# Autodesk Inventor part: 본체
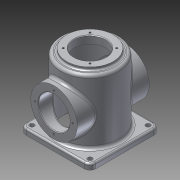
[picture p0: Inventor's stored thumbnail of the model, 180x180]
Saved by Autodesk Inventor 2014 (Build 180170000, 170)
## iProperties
Created: 2015-10
Part Number: 본체
Material: 알루미늄 6061
Document SubType Name: Modeling
Designer: USER
Density: 2.71 g/cm^3
Appearance: 알루미늄 - 평지
Mass: 982.687 g
Surface Area: 1041.97 cm^2
Volume: 362.615 cm^3
Author: USER
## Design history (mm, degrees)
sketch "스케치1"
  geometry: C1 r 50 at (0, 0); 1 further point
  constraints: 1 centre point, 1 coincident
  dimensions: "d0" = 100 diameter of C1
extrude "돌출1" new body sketch "스케치1" distance "d1" = 120; taper "d2" = 0 deg
sketch "스케치2"
  geometry: C1 r 50 at (0, 0) reference; C2 r 40 at (0, 0)
  constraints: 1 centre point, 1 coincident
  dimensions: "d3" = 80 diameter of C2
extrude "돌출2" join sketch "스케치2" distance "d4" = 5; taper "d5" = 0 deg
sketch "스케치3"
  geometry: C1 r 40 at (0, 0) reference; C2 r 27 at (0, 0)
  constraints: 1 centre point, 1 coincident
  dimensions: "d6" = 54 diameter of C2
extrude "돌출3" cut sketch "스케치3" distance "d7" = 13; taper "d8" = 0 deg
sketch "스케치4"
  geometry: C1 r 27 at (0, 0) reference; C2 r 45 at (0, 0)
  constraints: 1 centre point, 1 coincident
  dimensions: "d9" = 90 diameter of C2
extrude "돌출4" cut sketch "스케치4" distance "d10" = 112; taper "d11" = 0 deg
sketch "스케치5"
  geometry: L1 (-60, 60)-(60, 60); L2 (60, 60)-(60, -60); L3 (60, -60)-(-60, -60); L4 (-60, -60)-(-60, 60); C1 r 45 at (0, 0) reference; 2 further points
  constraints: 8 end point, 2 midpoint, 2 parallel, 1 horizontal, 1 horizontal alignment, 1 perpendicular, 1 vertical alignment
  dimensions: "d12" = 120 distance of L1.start L1.end; "d13" = 120 distance of L3.end L1.start
extrude "돌출5" join sketch "스케치5" distance "d14" = 10; taper "d15" = 0 deg
sketch "스케치6"
  geometry: L1 (0, 0)-(0, 32.5); L2 (0, 0)-(22.981, 22.981); C1 r 27 at (0, 0) reference; C2 r 40 at (0, 0) reference; A1 r 32.5 centre (0, 0) between (0, 32.5) and (22.981, 22.981); 1 further point
  constraints: 4 end point, 3 coincident, 2 point on circle, 1 centre point, 1 vertical
  dimensions: "d16" = 65 diameter of A1; "d17" = 45 deg angle of L2 L1
hole "구멍1" sketch "스케치6" at (22.981, 22.981) diameter "d18" = 3.242; stored, may be unused: countersink angle "d22" = 90 deg, drill point angle "d24" = 118 deg; dims "d19" = 8, "d20" = 4, "d21" = 2, "d23" = 10
sketch "스케치7"
  geometry: C1 r 50 at (0, 0) reference; C2 r 4 at (-50, 50); C3 r 4 at (50, 50); C4 r 4 at (50, -50); C5 r 4 at (-50, -50)
  constraints: 4 centre point
  dimensions: "d28" = 8 diameter of C2; "d29" = 8 diameter of C3; "d30" = 8 diameter of C4; "d31" = 8 diameter of C5; "d32" = 50 horizontal distance of C1.centre C2.centre; "d33" = 50 horizontal distance of C1.centre C3.centre; "d34" = 50 horizontal distance of C5.centre C1.centre; "d35" = 50 horizontal distance of C4.centre C1.centre; "d36" = 50 horizontal distance of C1.centre C2.centre; "d37" = 50 horizontal distance of C1.centre C3.centre; "d38" = 50 horizontal distance of C4.centre C1.centre; "d39" = 50 horizontal distance of C5.centre C1.centre
extrude "돌출6" cut sketch "스케치7" stored distance "d40" = 10; taper "d41" = 0 deg
fillet "모깎기1" dims "d42" = 10
node "작업 평면1"
sketch "스케치8"
  geometry: L1 (45, 0)-(-45, 0) reference; C1 r 40 at (0, 60); 2 further points
  constraints: 1 centre point, 1 midpoint, 1 vertical alignment
  dimensions: "d44" = 80 diameter of C1; "d45" = 60 distance from line of L1 C1.centre
extrude "돌출7" join sketch "스케치8" stored distance "d46" = 10; taper "d47" = 0 deg
fillet "모깎기2" dims "d48" = 3
fillet "모깎기4" dims "d50" = 5
sketch "스케치9"
  geometry: C1 r 40 at (0, 0) reference; C2 r 27 at (0, 0); 1 further point
  constraints: 1 centre point, 1 coincident
  dimensions: "d51" = 54 diameter of C2
extrude "돌출8" cut sketch "스케치9" stored distance "d52" = 10; taper "d53" = 0 deg
fillet "모깎기5" dims "d54" = 3
sketch "스케치10" dims "d55" = 65
  geometry: L1 (0, 0)-(0, 32.5); C1 r 40 at (0, 0) reference; 2 further points
  constraints: 2 coincident, 2 end point, 1 vertical, 1 vertical alignment, 2 other
hole "구멍2" sketch "스케치10" at (0, 32.5) diameter "d56" = 3.242; stored, may be unused: countersink angle "d60" = 90 deg, drill point angle "d62" = 118 deg; dims "d57" = 8, "d58" = 4, "d59" = 2, "d61" = 10
chamfer "모따기1" distance "d66" = 1; stored, may be unused: second distance "d67" = 2, angle "d68" = 45 deg
chamfer "모따기2" distance "d69" = 3; stored, may be unused: second distance "d70" = 2, angle "d71" = 45 deg
fillet "모깎기6" dims "d72" = 3
chamfer "모따기3" distance "d73" = 1; stored, may be unused: second distance "d74" = 2, angle "d75" = 45 deg
fillet "모깎기7" dims "d76" = 5
fillet "모깎기8" dims "d77" = 3
node "작업 평면5"
sketch "스케치13"
  geometry: 2 further points
  constraints: 1 vertical alignment, 1 other
  dimensions: "d83" = 70 distance of point (0, 0) point (0, 70)
feature "엠보싱1" sketch "스케치13" dims "d84" = 0.5, "d85" = 0
fillet "모깎기9" dims "d86" = 5
node "솔리드1"
pattern_circular "원형 패턴1" dims angle "d26" = 360 deg
pattern_circular "원형 패턴2" dims angle "d64" = 360 deg
mirror "대칭1"
node "작업 평면2"
other parameters: "d43" = 62
